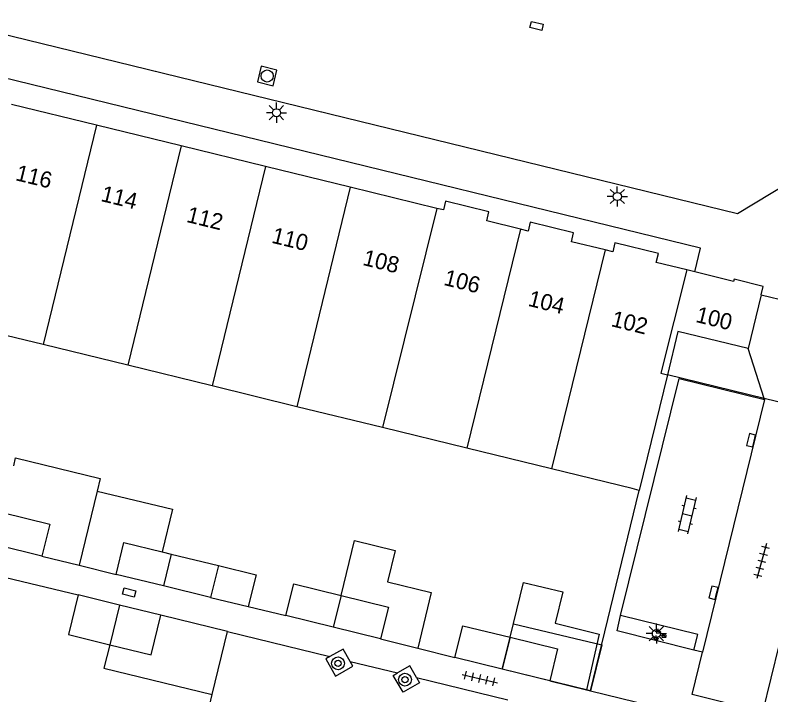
# Model space of a CAD drawing. Extents: x 125000 to 129004, y 397500 to 399008.
# Drawn here: x 126436.93 to 126483.68, y 398378.95 to 398421.04 of the extents above; entities that cross this region are included whole.
import ezdxf

# ---------------------------------------------------------------- set-up
doc = ezdxf.new("R2010")
doc.units = 0
for name, color, linetype in [('gg-afsc-erfafscheiding', 7, 'Continuous'), ('gg-afsc-hekwerk', 7, 'Continuous'), ('gg-anno-huisnummerreeks BGT', 7, 'Continuous'), ('gg-bbg-bijgebouw', 7, 'Continuous'), ('gg-bbg-hoofdgebouw', 7, 'Continuous'), ('gg-bbg-luifel en loopbrug', 7, 'Continuous'), ('gg-bbg-onder overbouw', 7, 'Continuous'), ('gg-bbg-pand overbouw', 7, 'Continuous'), ('gg-bbg-tussenscheiding', 7, 'Continuous'), ('gg-knt-verharding', 7, 'Continuous'), ('gt-bbg-plantopografie pand', 7, 'Continuous'), ('gt-grn-weggrens', 7, 'Continuous'), ('gt-symb-boom', 7, 'Continuous'), ('gt-symb-groenvak', 7, 'Continuous'), ('gt-symb-klinker verharding', 7, 'Continuous'), ('gt-symb-kolk', 7, 'Continuous'), ('gt-symb-kolk center center', 7, 'Continuous'), ('gt-symb-lichtmast', 7, 'Continuous'), ('gt-symb-rioolschacht', 7, 'Continuous'), ('gt-symb-tegel verharding', 7, 'Continuous')]:
    doc.layers.add(name, color=color, linetype=linetype)

# ---------------------------------------------------------------- blocks, each defined once
blk = doc.blocks.new('gt0-KOLKCC')
at = {"layer": 'gt-symb-kolk center center'}
blk.add_lwpolyline([(-0.375, 0.2), (0.375, 0.2), (0.375, -0.2), (-0.375, -0.2)], close=True, dxfattribs=at)
blk = doc.blocks.new('gt0-RS')
at = {"layer": 'gt-symb-rioolschacht'}
blk.add_lwpolyline([(-0.5, -0.5), (0.5, -0.5), (0.5, 0.5), (-0.5, 0.5)], close=True, dxfattribs=at)
blk.add_circle((0, 0), 0.375, dxfattribs=at)
blk = doc.blocks.new('gt0-LMAST')
at = {"layer": 'gt-symb-lichtmast'}
for p, q in [((-0.005, 0.246), (-0.005, 0.621)), ((-0.182, 0.173), (-0.447, 0.438)), ((0.172, 0.173), (0.437, 0.438)), ((-0.255, -0.004), (-0.63, -0.004)), ((-0.182, -0.181), (-0.447, -0.446)), ((-0.005, -0.254), (-0.005, -0.629)), ((0.437, -0.446), (0.172, -0.181)), ((0.245, -0.004), (0.62, -0.004))]:
    blk.add_line(p, q, dxfattribs=at)
blk.add_circle((-0.005, -0.004), 0.25, dxfattribs=at)
blk = doc.blocks.new('gt0-BOOM')
at = {"layer": 'gt-symb-boom'}
for radius in [0.4, 0.2]:
    blk.add_circle((0, 0), radius, dxfattribs=at)
blk = doc.blocks.new('gt0-KOLK')
at = {"layer": 'gt-symb-kolk'}
blk.add_lwpolyline([(0, 0), (0.375, 0), (0.375, 0.4), (-0.375, 0.4), (-0.375, 0), (0, 0)], dxfattribs=at)
blk = doc.blocks.new('gt0-TEG1')
at = {"layer": 'gt-symb-tegel verharding'}
for p, q in [((-1.125, 0), (1.125, 0)), ((-0.9, -0.25), (-0.9, 0.25)), ((-0.45, -0.25), (-0.45, 0.25)), ((0, -0.25), (0, 0.25)), ((0.45, -0.25), (0.45, 0.25)), ((0.9, -0.25), (0.9, 0.25))]:
    blk.add_line(p, q, dxfattribs=at)
blk = doc.blocks.new('gt0-KL1')
at = {"layer": 'gt-symb-klinker verharding'}
for p, q in [((-1.15, 0.3), (1.15, 0.3)), ((-1, -0.3), (-1, 0.3)), ((-0.5, 0.3), (-0.5, 0.45)), ((0, -0.3), (0, 0.3)), ((0.5, 0.3), (0.5, 0.45)), ((1, -0.3), (1, 0.3)), ((-1.15, -0.3), (1.15, -0.3)), ((-0.5, -0.45), (-0.5, -0.3)), ((0.5, -0.45), (0.5, -0.3))]:
    blk.add_line(p, q, dxfattribs=at)
blk = doc.blocks.new('gt0-GRVAK')
at = {"layer": 'gt-symb-groenvak'}
for p, q in [((-0.11, 0.189), (-0.228, 0.24)), ((-0.182, 0.153), (0.088, 0.153)), ((-0.091, 0.211), (-0.156, 0.322)), ((-0.047, 0.214), (-0.047, 0.393)), ((-0.004, 0.211), (0.061, 0.322)), ((0.015, 0.189), (0.133, 0.24)), ((0.262, -0.052), (0.197, 0.059)), ((0.305, -0.049), (0.305, 0.13)), ((0.349, -0.052), (0.414, 0.059)), ((-0.245, -0.228), (-0.363, -0.177)), ((-0.318, -0.264), (-0.047, -0.264)), ((-0.226, -0.206), (-0.291, -0.095)), ((-0.183, -0.203), (-0.183, -0.024)), ((-0.139, -0.206), (-0.074, -0.095)), ((-0.12, -0.228), (-0.002, -0.177)), ((0.243, -0.074), (0.125, -0.023)), ((0.17, -0.11), (0.441, -0.11)), ((0.368, -0.074), (0.486, -0.023))]:
    blk.add_line(p, q, dxfattribs=at)

msp = doc.modelspace()

# ---------------------------------------------------------------- linework, layer by layer
at = {"layer": 'gg-afsc-erfafscheiding'}
for p, q in [((126435.457, 398386.425), (126440.82, 398385.139)), ((126451.349, 398384.431), (126453.679, 398383.875)), ((126461.833, 398381.84), (126464.135, 398381.265)), ((126472.517, 398379.207), (126478.224, 398377.82))]:
    msp.add_line(p, q, dxfattribs=at)
at = {"layer": 'gg-afsc-hekwerk'}
for p, q in [((126472.517, 398379.207), (126475.527, 398391.614)), ((126472.274, 398379.263), (126472.517, 398379.207)), ((126447.733, 398373.254), (126449.123, 398378.975))]:
    msp.add_line(p, q, dxfattribs=at)
at = {"layer": 'gg-bbg-bijgebouw'}
for p, q in [((126438.584, 398387.541), (126435.656, 398388.268)), ((126446.022, 398387.801), (126446.581, 398387.665)), ((126446.581, 398387.665), (126449.512, 398386.953)), ((126449.512, 398386.953), (126449.019, 398384.987)), ((126446.099, 398385.699), (126443.179, 398386.411)), ((126449.019, 398384.987), (126446.099, 398385.699)), ((126443.381, 398384.515), (126440.82, 398385.139)), ((126445.942, 398383.89), (126443.381, 398384.515)), ((126456.605, 398383.145), (126453.679, 398383.875)), ((126459.531, 398382.415), (126456.605, 398383.145)), ((126467.066, 398380.542), (126464.135, 398381.265)), ((126469.996, 398379.819), (126467.066, 398380.542))]:
    msp.add_line(p, q, dxfattribs=at)
for points in [[(126436.139, 398390.241), (126439.077, 398389.514), (126438.584, 398387.541)], [(126443.179, 398386.411), (126443.643, 398388.379), (126446.022, 398387.801)], [(126453.679, 398383.875), (126454.165, 398385.831), (126457.091, 398385.108)], [(126440.82, 398385.139), (126440.221, 398382.681), (126442.778, 398382.06)], [(126457.091, 398385.108), (126460.017, 398384.385), (126459.531, 398382.415)], [(126442.778, 398382.06), (126445.334, 398381.439), (126445.942, 398383.89)], [(126464.135, 398381.265), (126464.618, 398383.23), (126467.549, 398382.516)], [(126467.549, 398382.516), (126470.48, 398381.801), (126469.996, 398379.819)]]:
    msp.add_lwpolyline(points, dxfattribs=at)
at = {"layer": 'gg-bbg-hoofdgebouw'}
for p, q in [((126441.969, 398414.219), (126436.711, 398415.504)), ((126447.198, 398412.941), (126441.969, 398414.219)), ((126452.416, 398411.665), (126447.198, 398412.941)), ((126457.662, 398410.382), (126452.416, 398411.665)), ((126463.024, 398409.071), (126457.662, 398410.382)), ((126478.982, 398405.136), (126478.476, 398405.26)), ((126438.665, 398400.638), (126433.407, 398401.925)), ((126443.894, 398399.358), (126438.665, 398400.638)), ((126449.111, 398398.081), (126443.894, 398399.358)), ((126477.278, 398398.774), (126475.527, 398391.614)), ((126454.357, 398396.796), (126449.111, 398398.081)), ((126459.663, 398395.498), (126454.357, 398396.796)), ((126464.867, 398394.224), (126459.663, 398395.498)), ((126470.103, 398392.942), (126464.867, 398394.224)), ((126475.093, 398391.72), (126470.103, 398392.942)), ((126475.527, 398391.614), (126475.093, 398391.72))]:
    msp.add_line(p, q, dxfattribs=at)
for points in [[(126468.188, 398407.783), (126466.1, 398408.295), (126466.238, 398408.86), (126463.558, 398409.512), (126463.426, 398408.973), (126463.024, 398409.071)], [(126473.425, 398406.5), (126471.344, 398407.009), (126471.479, 398407.567), (126468.793, 398408.216), (126468.66, 398407.667), (126468.188, 398407.783)], [(126478.476, 398405.26), (126476.587, 398405.723), (126476.723, 398406.284), (126474.034, 398406.938), (126473.9, 398406.384), (126473.425, 398406.5)], [(126483.07, 398403.717), (126483.194, 398404.237), (126481.398, 398404.687), (126481.364, 398404.551), (126478.982, 398405.136)]]:
    msp.add_lwpolyline(points, dxfattribs=at)
at = {"layer": 'gg-bbg-luifel en loopbrug'}
for p, q in [((126442.188, 398392.352), (126441.999, 398391.574)), ((126441.999, 398391.574), (126440.882, 398386.976)), ((126438.584, 398387.541), (126440.882, 398386.976)), ((126440.882, 398386.976), (126443.179, 398386.411)), ((126449.019, 398384.987), (126451.349, 398384.431)), ((126450.071, 398382.873), (126445.942, 398383.89)), ((126449.123, 398378.975), (126450.071, 398382.873)), ((126459.531, 398382.415), (126461.833, 398381.84)), ((126469.996, 398379.819), (126472.274, 398379.263))]:
    msp.add_line(p, q, dxfattribs=at)
for points in [[(126436.842, 398393.136), (126436.96, 398393.622), (126442.188, 398392.352)], [(126441.999, 398391.574), (126446.663, 398390.441), (126446.022, 398387.801)], [(126457.091, 398385.108), (126457.917, 398388.509), (126460.444, 398387.895), (126459.972, 398385.952), (126462.673, 398385.296), (126461.833, 398381.84)], [(126449.512, 398386.953), (126451.829, 398386.39), (126451.349, 398384.431)], [(126467.549, 398382.516), (126468.375, 398385.917), (126470.805, 398385.327), (126470.332, 398383.383), (126473.053, 398382.722), (126472.274, 398379.263)], [(126442.778, 398382.06), (126442.424, 398380.602), (126449.123, 398378.975)]]:
    msp.add_lwpolyline(points, dxfattribs=at)
at = {"layer": 'gg-bbg-onder overbouw'}
msp.add_line((126483.07, 398403.717), (126482.278, 398400.401), dxfattribs=at)
msp.add_lwpolyline([(126482.278, 398400.401), (126477.93, 398401.44), (126477.278, 398398.774)], dxfattribs=at)
at = {"layer": 'gg-bbg-pand overbouw'}
for p, q in [((126483.07, 398403.717), (126486.986, 398402.757)), ((126483.256, 398397.304), (126477.278, 398398.774)), ((126485.486, 398396.755), (126483.256, 398397.304))]:
    msp.add_line(p, q, dxfattribs=at)
at = {"layer": 'gg-bbg-tussenscheiding'}
for p, q in [((126441.969, 398414.219), (126438.665, 398400.638)), ((126447.198, 398412.941), (126443.894, 398399.358)), ((126452.416, 398411.665), (126449.111, 398398.081)), ((126457.662, 398410.382), (126454.357, 398396.796)), ((126463.024, 398409.071), (126459.663, 398395.498)), ((126468.188, 398407.783), (126464.867, 398394.224)), ((126473.425, 398406.5), (126470.103, 398392.942)), ((126446.581, 398387.665), (126446.099, 398385.699)), ((126457.091, 398385.108), (126456.605, 398383.145)), ((126443.381, 398384.515), (126442.778, 398382.06)), ((126467.549, 398382.516), (126467.066, 398380.542))]:
    msp.add_line(p, q, dxfattribs=at)
msp.add_lwpolyline([(126478.476, 398405.26), (126476.88, 398398.872), (126477.278, 398398.774)], dxfattribs=at)
at = {"layer": 'gg-knt-verharding'}
for p, q in [((126483.275, 398397.243), (126479.439, 398381.603)), ((126450.071, 398382.873), (126456.405, 398381.331)), ((126479.439, 398381.603), (126478.921, 398381.728)), ((126457.646, 398381.029), (126460.585, 398380.314)), ((126461.756, 398380.028), (126467.41, 398378.652))]:
    msp.add_line(p, q, dxfattribs=at)
for points in [[(126416.713, 398429.094), (126419.862, 398423.885), (126481.608, 398408.756), (126486.866, 398411.927)], [(126478.982, 398405.136), (126479.329, 398406.612), (126420.94, 398420.898), (126420.559, 398419.465)], [(126474.379, 398383.866), (126478.013, 398398.538), (126483.275, 398397.243)], [(126487.649, 398396.223), (126487.025, 398393.613), (126484.697, 398384.195), (126483.165, 398377.891)], [(126478.921, 398381.728), (126474.163, 398382.925), (126474.379, 398383.866)], [(126478.921, 398381.728), (126479.169, 398382.692), (126474.379, 398383.866)], [(126457.646, 398381.029), (126457.215, 398381.79), (126456.405, 398381.331)], [(126456.405, 398381.331), (126456.145, 398381.184), (126456.748, 398380.117), (126457.819, 398380.723), (126457.646, 398381.029)], [(126461.756, 398380.028), (126461.34, 398380.751), (126460.585, 398380.314)], [(126461.756, 398380.028), (126461.942, 398379.705), (126460.925, 398379.117), (126460.321, 398380.161), (126460.585, 398380.314)]]:
    msp.add_lwpolyline(points, dxfattribs=at)
at = {"layer": 'gt-bbg-plantopografie pand'}
msp.add_lwpolyline([(126467.763, 398383.346), (126473.225, 398382.053), (126472.517, 398379.207), (126467.066, 398380.542), (126467.753, 398383.349), (126467.763, 398383.346)], dxfattribs=at)
at = {"layer": 'gt-grn-weggrens'}
for p, q in [((126483.256, 398397.304), (126482.278, 398400.401)), ((126483.275, 398397.243), (126483.256, 398397.304))]:
    msp.add_line(p, q, dxfattribs=at)
msp.add_lwpolyline([(126483.165, 398377.891), (126478.816, 398378.979), (126479.439, 398381.603)], dxfattribs=at)

# ---------------------------------------------------------------- block references
at = {"layer": 'gt-symb-boom'}
for p in [(126456.901, 398380.907), (126461.045, 398379.896)]:
    msp.add_blockref('gt0-BOOM', p, dxfattribs=at)
at = {"layer": 'gt-symb-groenvak'}
msp.add_blockref('gt0-GRVAK', (126476.756, 398382.646), dxfattribs=at)
at = {"layer": 'gt-symb-klinker verharding', "rotation": -103.11914463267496}
msp.add_blockref('gt0-KL1', (126478.496, 398390.111), dxfattribs=at)
at = {"layer": 'gt-symb-kolk'}
for p, rotation in [((126482.646, 398394.666), 76.29711003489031), ((126480.32, 398385.231), 76.17220496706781)]:
    msp.add_blockref('gt0-KOLK', p, dxfattribs=dict(at, rotation=rotation))
at = {"layer": 'gt-symb-kolk center center'}
for p, rotation in [((126469.188, 398420.366), 166.35276166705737), ((126443.99, 398385.293), -15.189787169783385)]:
    msp.add_blockref('gt0-KOLKCC', p, dxfattribs=dict(at, rotation=rotation))
at = {"layer": 'gt-symb-lichtmast'}
for p in [(126453.1, 398414.996), (126474.185, 398409.811), (126476.601, 398382.755)]:
    msp.add_blockref('gt0-LMAST', p, dxfattribs=at)
at = {"layer": 'gt-symb-rioolschacht', "rotation": 76.51987378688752}
msp.add_blockref('gt0-RS', (126452.523, 398417.268), dxfattribs=at)
at = {"layer": 'gt-symb-tegel verharding'}
for p, rotation in [((126483.106, 398387.234), -105.11952547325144), ((126465.669, 398379.962), -13.299584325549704)]:
    msp.add_blockref('gt0-TEG1', p, dxfattribs=dict(at, rotation=rotation))

# ---------------------------------------------------------------- texts
at = {"layer": 'gg-anno-huisnummerreeks BGT'}
for s, rotation, p in [('116', 346.3, (126436.9, 398410.824)), ('114', 346.3, (126442.18, 398409.534)), ('112', 346.2, (126447.475, 398408.241)), ('110', 346.2, (126452.739, 398406.954)), ('108', 346.2, (126458.376, 398405.576)), ('106', 346, (126463.386, 398404.343)), ('104', 346.2, (126468.604, 398403.048)), ('102', 346.2, (126473.746, 398401.787)), ('100', 346.2, (126478.973, 398402.049))]:
    msp.add_text(s, height=1, rotation=rotation, dxfattribs=at).set_placement(p)

doc.saveas('drawing.dxf')
